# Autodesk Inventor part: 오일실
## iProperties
IsCustomPart: 0
Manager: KYOUNG IL JANG
Company: 한국ATC센터
Created: 2009-02
Part Number: 오일실
Material: 고무
Description: 오일-실
Document SubType Name: Modeling
Standard: KS B 2804
Standards Organization: KS
Language: ko-KR
Size Designation: D - 20 35 8
Categories: <MemberInstance><Categories><Category DisplayName="샤프트 부품" InternalName="7f7aeb1f-a693-4053-b835-cee3144e0d98" Mnemonic="SHFT"><Category DisplayName="실링" Intern
Density: 0.93 g/cm^3
Checked By: KYOUNG IL JANG
Vendor: CBT Solutions
Designer: KYOUNG IL JANG
Author: KYOUNG IL JANG
